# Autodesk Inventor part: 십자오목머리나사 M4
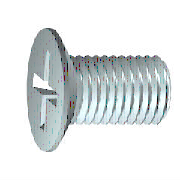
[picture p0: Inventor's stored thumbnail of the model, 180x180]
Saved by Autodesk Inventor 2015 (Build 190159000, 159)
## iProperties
IsCustomPart: 0
Created: 2012-02
Part Number: 십자오목머리나사 M4
Material: 강철, 연강
Description: 십자 오목 머리 나사
Document SubType Name: Modeling
Standard: KS B 1023
Designer: mduedu
Standards Organization: KS
Language: ko-KR
Size Designation: A  M 4 x 12 - H
Categories: <MemberInstance><Categories><Category DisplayName="조임쇠" InternalName="e4da775c-781d-43d5-af7c-5136215cf5a6" Mnemonic="FSTN"><Category DisplayName="볼트" InternalN
Density: 7.86 g/cm^3
Mass: 1.50482 g
Surface Area: 2.78557 cm^2
Volume: 0.191453 cm^3
Appearance: 주황색
Author: mduedu
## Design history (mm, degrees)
body "Solid1"
sketch "스케치1"
  geometry: L1 (2.6, 0)-(12, 0); L2 (12, 0)-(12, 2); L3 (12, 2)-(4.1, 2); L4 (4.1, 2)-(3.671, 1.785); L5 (3.671, 1.785)-(2.7, 1.785); L6 (0, 4.2)-(0, 2.4); L7 (0, 2.4)-(1.801, 1.502); L8 (1.801, 1.502)-(2.6, 0); L9 (-2.4, 0)-(14.4, 0) reference; L10 (0, -0.84)-(0, 5.04) reference; L11 (0, 4.2)-(0.285, 4.2); L12 (0.285, 4.2)-(2.7, 1.785); L13 (4.1, 2)-(2.485, 2)
  constraints: 22 end point, 3 parallel, 3 perpendicular, 2 collinear, 1 horizontal, 1 point on line
  dimensions: "d1" = 7.9 distance of L2.end L3.end (= GEL); "d2" = 4 diameter of L3 L1 (= GD); "d3" = 3.57058 diameter of L5 L1 (= BDM); "d4" = 4.8 diameter of L6.end L1 (= SDM); "d5" = 26.5 deg angle of L7 L1; "d6" = 62 deg angle of L8 L1; "d7" = 2.6 distance from line of L1.start L6 (= INTI); "d8" = 0.42941 horizontal distance of L4.end L3.end (= GAL); "d12" = 8.4 diameter of L11 L1 (= KOD); "d13" = 45 deg angle of L12 L1 (= 0.5 x SEWI); "d15" = 12 distance between parallel lines of L2 L6 (= NLG); "d24" = 2.7 distance from line of L5.end L6 (= KOH)
revolve "본체" stored, may be unused: angle "d16" = 90 deg
sketch "스케치2"
  geometry: L1 (0, 2.4)-(0, 0); L2 (0, 0)-(2.4, 0); L3 (0, 0)-(1.697, 1.697); L4 (0.312, 2.38)-(0.408, 0.734); L5 (2.38, 0.312)-(0.734, 0.408); L6 (0, -5.88)-(0, 5.88) reference; L7 (-5.88, 0)-(5.88, 0) reference; L8 (2.38, -0.312)-(0.734, -0.408); L9 (0.312, -2.38)-(0.408, -0.734); L10 (-0.312, -2.38)-(-0.408, -0.734); L11 (-2.38, -0.312)-(-0.734, -0.408); L12 (-2.38, 0.312)-(-0.734, 0.408); L13 (-0.312, 2.38)-(-0.408, 0.734); A1 r 0.72 centre (0, 0) between (0.72, 0) and (0, 0.72); A2 r 0.84 centre (0, 0) between (0.84, 0) and (0, 0.84); A3 r 2.4 centre (0, 0) between (2.38, 0.312) and (0.312, 2.38); A4 r 2.4 centre (0, 0) between (0.312, 2.38) and (0, 2.4); A5 r 2.4 centre (0, 0) between (2.4, 0) and (2.38, 0.312); A6 r 2.4 centre (0, 0) between (0, -2.4) and (0.312, -2.38); A7 r 2.4 centre (0, 0) between (0.312, -2.38) and (2.38, -0.312); A8 r 2.4 centre (0, 0) between (2.38, -0.312) and (2.4, 0); A9 r 2.4 centre (0, 0) between (0, 2.4) and (-0.312, 2.38); A10 r 2.4 centre (0, 0) between (-0.312, 2.38) and (-2.38, 0.312); A11 r 2.4 centre (0, 0) between (-2.38, 0.312) and (-2.4, 0); A12 r 2.4 centre (0, 0) between (-2.4, 0) and (-2.38, -0.312); A13 r 2.4 centre (0, 0) between (-2.38, -0.312) and (-0.312, -2.38); A14 r 2.4 centre (0, 0) between (-0.312, -2.38) and (0, -2.4); A15 r 0.347 centre (0.755, 0.755) between (0.408, 0.734) and (0.734, 0.408); A16 r 0.347 centre (0.755, -0.755) between (0.734, -0.408) and (0.408, -0.734); A17 r 0.347 centre (-0.755, -0.755) between (-0.408, -0.734) and (-0.734, -0.408); A18 r 0.347 centre (-0.755, 0.755) between (-0.734, 0.408) and (-0.408, 0.734); 3 further points
  constraints: 41 point on circle, 22 end point, 22 symmetric about line, 18 centre point, 11 coincident, 4 point on line, 3 tangent, 2 collinear, 1 perpendicular, 1 vertical, 19 other
  dimensions: "d17" = 1.44 diameter of A1 (= 0.3 x SDM); "d18" = 1.68 diameter of A2 (= 0.35 x SDM); "d19" = 4.8 diameter of A3 (= SDM); "d20" = 45 deg angle of L3 L2; "d21" = 0.3115 distance from line of L4.start L1 (= 0.5 x SBR)
extrude "슬롯" join sketch "스케치2" taper "d22" = 5 deg; stored distance "d79" = 25.4
fillet "모깎기1" dims "d23" = 0.1246 (= 0.2 x SBR)
feature "스레드" dims "d10" = 7.9 (= GEL), "d11" = 0
chamfer "모따기1" distance "d25" = 0.42941 (= -0.5 x SPD + 0.5 x GD); stored, may be unused: second distance "d26" = 0.21471 (= 0.5 x GAL), angle "d88" = 45 deg
workplane "Work Plane2"
other parameters: "NLG" = 12 [user parameter; used in 1 equation term], "GEL" = 7.9 [user parameter; used in 2 equation terms], "GAL" = 0.42941 (= 0.61345 x PTC) [user parameter; used in 3 equation terms], "SPD" = 3.14117 (= NND - 1.2269 x PTC) [user parameter; used in 1 equation term], "KOD" = 8.4 [user parameter; used in 1 equation term], "KOH" = 2.7 [user parameter; used in 1 equation term], "SBR" = 0.623 [user parameter; used in 2 equation terms], "INTI" = 2.6 [user parameter; used in 1 equation term], "SDM" = 4.8 [user parameter; used in 5 equation terms], "GD" = 4 (= NND) [user parameter; used in 2 equation terms], "BDM" = 3.57058 (= NND - GAL) [user parameter; used in 1 equation term], "SEWI" = 90 deg [user parameter; used in 1 equation term], "d9" = 4.8 (= SDM), "d27" = 0, "d91" = 0, "d92" = 0, "GUL" = 0.42941 (= 0.61345 x PTC) [user parameter], "TOA" = 30 deg [user parameter], "EPV" = 4.7 [user parameter], "THREADDIA" = 4 [user parameter; used in 1 equation term], "TPU" = 14.28571 (computed from PTC) [user parameter], "PTC" = 0.7 [user parameter; used in 5 equation terms], "NND" = 4 [user parameter; used in 3 equation terms], "GD1" = 3.14117 (= THREADDIA - 1.2269 x PTC) [user parameter]
